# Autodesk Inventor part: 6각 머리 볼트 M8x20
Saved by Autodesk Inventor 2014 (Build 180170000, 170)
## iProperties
Created: 2026-04
Part Number: 6각 머리 볼트 M8x20
Material: 일반
Document SubType Name: Modeling
Designer: dg
Density: 1 g/cm^3
Appearance: 기본값
Author: dg
Author: jhkim
Description: 6각 머리 볼트 및 6각 머리 나사
Creation Date: 2026-03-27
Sending System: Autodesk Inventor 2026
Preprocessor: ST-DEVELOPER v20.1
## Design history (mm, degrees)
node "6각 머리 볼트 M8x201"
body "Solid1"
node "기준1"
